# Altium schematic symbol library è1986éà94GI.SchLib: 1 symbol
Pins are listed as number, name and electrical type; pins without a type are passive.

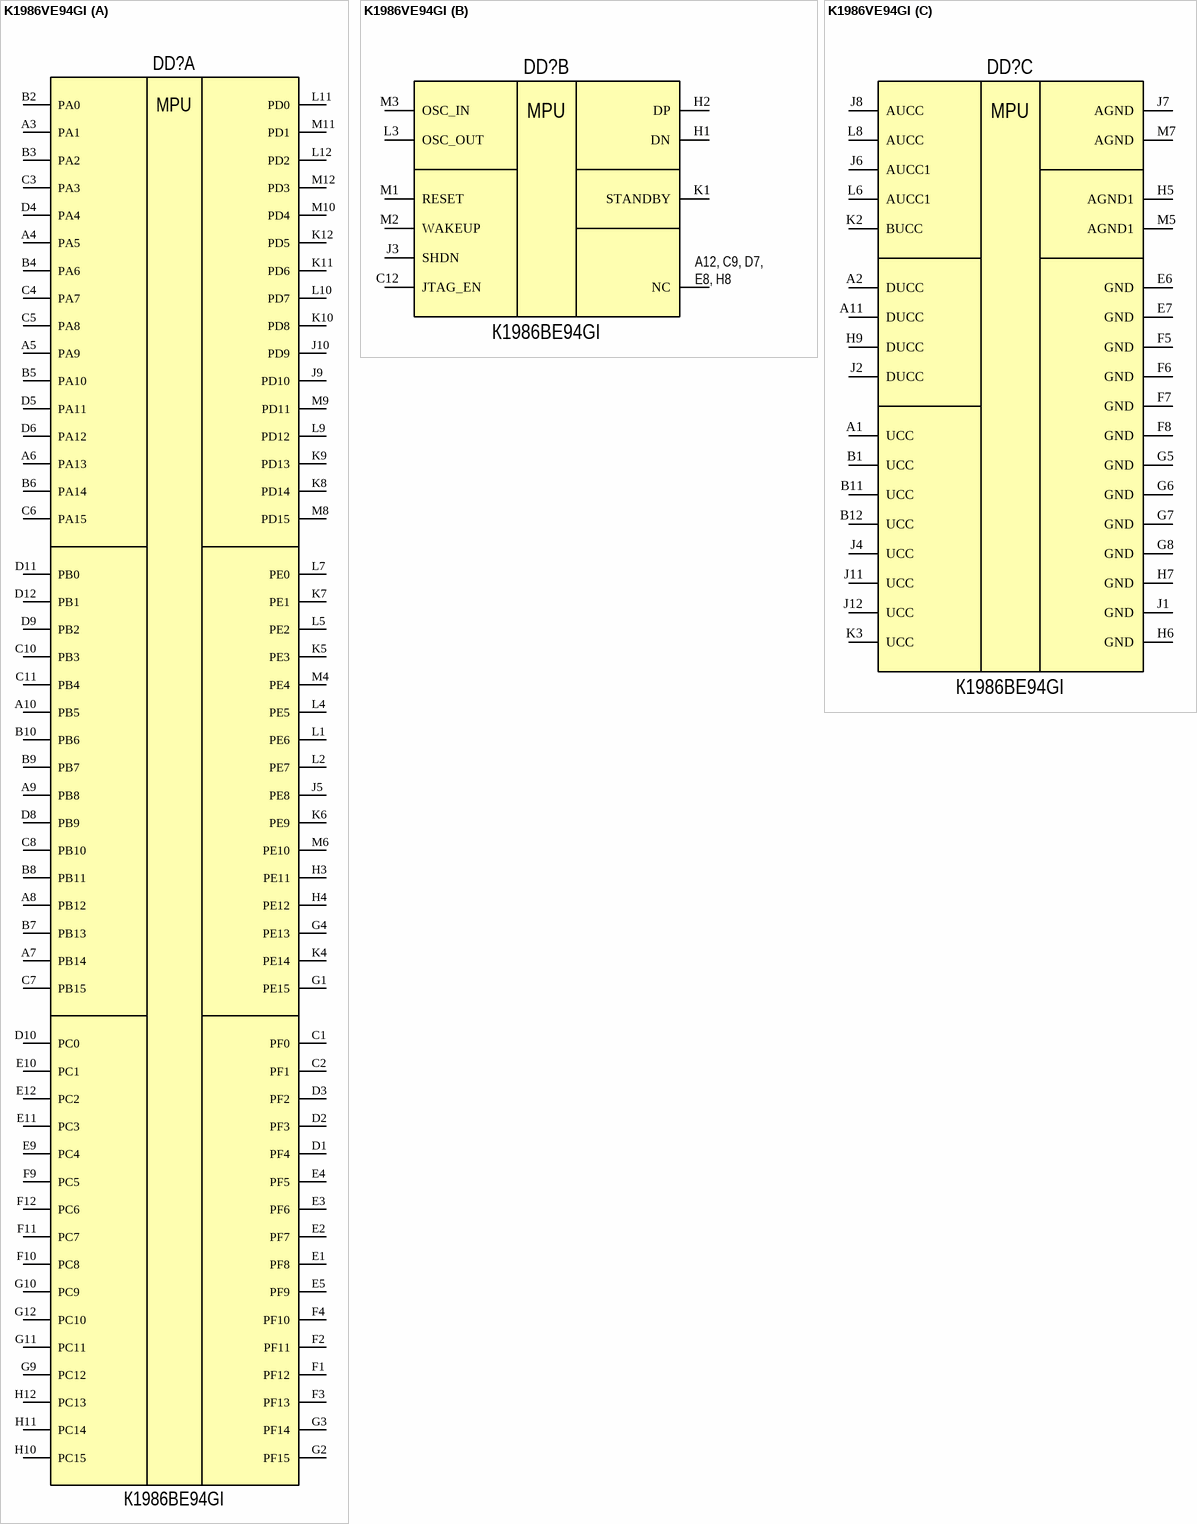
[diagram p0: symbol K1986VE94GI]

## K1986VE94GI
designator DD?
part A pins: A3 PA1, A4 PA5, A5 PA9, A6 PA13, A7 PB14, A8 PB12, A9 PB8, A10 PB5, B2 PA0, B3 PA2, B4 PA6, B5 PA10, B6 PA14, B7 PB13, B8 PB11, B9 PB7, B10 PB6, C1 PF0, C2 PF1, C3 PA3, C4 PA7, C5 PA8, C6 PA15, C7 PB15, C8 PB10, C10 PB3, C11 PB4, D1 PF4, D2 PF3, D3 PF2, D4 PA4, D5 PA11, D6 PA12, D8 PB9, D9 PB2, D10 PC0, D11 PB0, D12 PB1, E1 PF8, E2 PF7, E3 PF6, E4 PF5, E5 PF9, E9 PC4, E10 PC1, E11 PC3, E12 PC2, F1 PF12, F2 PF11, F3 PF13, F4 PF10, F9 PC5, F10 PC8, F11 PC7, F12 PC6, G1 PE15, G2 PF15, G3 PF14, G4 PE13, G9 PC12, G10 PC9, G11 PC11, G12 PC10, H3 PE11, H4 PE12, H10 PC15, H11 PC14, H12 PC13, J5 PE8, J9 PD10, J10 PD9, K4 PE14, K5 PE3, K6 PE9, K7 PE1, K8 PD14, K9 PD13, K10 PD8, K11 PD6, K12 PD5, L1 PE6, L2 PE7, L4 PE5, L5 PE2, L7 PE0, L9 PD12, L10 PD7, L11 PD0, L12 PD2, M4 PE4, M6 PE10, M8 PD15, M9 PD11, M10 PD4, M11 PD1, M12 PD3
part B pins: A12 NC, C12 JTAG_EN, H1 DN, H2 DP, J3 SHDN, K1 STANDBY, L3 OSC_OUT, M1 RESET, M2 WAKEUP, M3 OSC_IN
part C pins: A1 UCC, A2 DUCC, A11 DUCC, B1 UCC, B11 UCC, B12 UCC, E6 GND, E7 GND, F5 GND, F6 GND, F7 GND, F8 GND, G5 GND, G6 GND, G7 GND, G8 GND, H5 AGND1, H6 GND, H7 GND, H9 DUCC, J1 GND, J2 DUCC, J4 UCC, J6 AUCC1, J7 AGND, J8 AUCC, J11 UCC, J12 UCC, K2 BUCC, K3 UCC, L6 AUCC1, L8 AUCC, M5 AGND1, M7 AGND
